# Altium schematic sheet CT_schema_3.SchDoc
size 207 x 169 mm
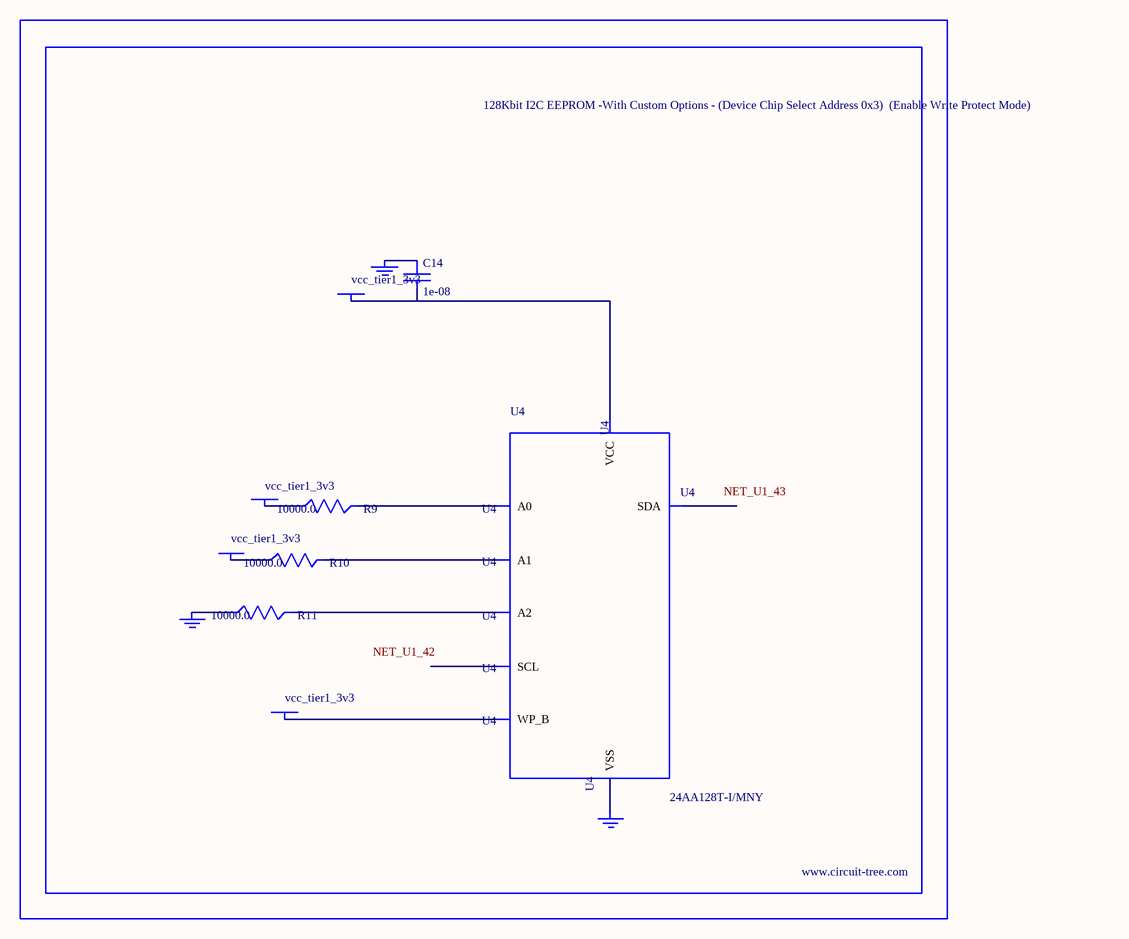
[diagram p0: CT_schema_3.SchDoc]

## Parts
BORDER2  (no value)
C14  1e-08  [C0402]
GND_INSTANCE_2_0  (no value)
GND_INSTANCE_2_1  (no value)
GND_INSTANCE_2_2  (no value)
POWER_INSTANCE_2_0  vcc_tier1_3v3
POWER_INSTANCE_2_1  vcc_tier1_3v3
POWER_INSTANCE_2_2  vcc_tier1_3v3
POWER_INSTANCE_2_3  vcc_tier1_3v3
R9  10000.0  [R0603]
R10  10000.0  [R0603]
R11  10000.0  [R0603]
U4  24AA128T-I/MNY  [TDFN-8/6MM]

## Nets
NetC14_1: C14.1 GND_INSTANCE_2_1.0(GND)
NetC14_2: C14.2 POWER_INSTANCE_2_3.0(PWR) U4.8(VCC)
NetGND_INSTANCE_2_0_0: GND_INSTANCE_2_0.0(GND) R11.1
NetGND_INSTANCE_2_2_0: GND_INSTANCE_2_2.0(GND) U4.4(VSS)
NetPOWER_INSTANCE_2_0_0: POWER_INSTANCE_2_0.0(PWR) R9.1
NetPOWER_INSTANCE_2_1_0: POWER_INSTANCE_2_1.0(PWR) R10.1
NetPOWER_INSTANCE_2_2_0: POWER_INSTANCE_2_2.0(PWR) U4.7(WP_B)
NetR9_2: R9.2 U4.1(A0)
NetR10_2: R10.2 U4.2(A1)
NetR11_2: R11.2 U4.3(A2)

Not connected (* = marked no-connect by the designer): U4 5(SDA) 6(SCL)

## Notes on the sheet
- Labels drawn without touching a wire or pin: NET_U1_42, NET_U1_43

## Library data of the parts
BORDER2 = BORDER_PAGE2
C14 = C0402C103K3RAC
GND_INSTANCE_2_0-GND_INSTANCE_2_2 = GND
POWER_INSTANCE_2_0-POWER_INSTANCE_2_3 = PWR
R9-R11 = RC0603JR-0710KL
